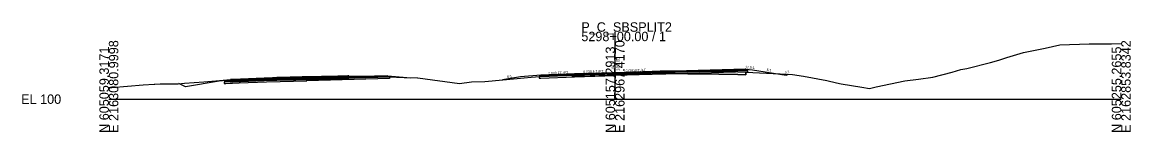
# Model space of a CAD drawing. Extents: x -26 to 1303, y -10 to 12033.
# Drawn here: x -25.7 to 302.8, y 9490.3 to 9522.8 of the extents above; entities that cross this region are included whole.
import ezdxf

# ---------------------------------------------------------------- set-up
doc = ezdxf.new("R2010")
doc.units = 0
for name, color, linetype in [('RD_GPK_XS_Cell', 7, 'Continuous'), ('RD_XS_Base', 7, 'Continuous'), ('RD_XS_ExGround', 7, 'Continuous'), ('RD_XS_ExPaveRet', 7, 'Continuous'), ('RD_XS_Greenside', 7, 'Continuous'), ('RD_XS_Pave', 7, 'Continuous'), ('RD_XS_PaveOvlay_CP', 7, 'Continuous'), ('RD_XS_TieSlope', 7, 'Continuous'), ('RD_XS_TX_Elev_EX', 7, 'Continuous'), ('RD_XS_TX_Elev_PR', 7, 'Continuous'), ('RD_XS_TX_ShdSlope', 7, 'Continuous'), ('RD_XS_TX_Slope', 7, 'Continuous')]:
    doc.layers.add(name, color=color, linetype=linetype)

msp = doc.modelspace()

# ---------------------------------------------------------------- linework, layer by layer
at = {"layer": 'RD_GPK_XS_Cell'}
for p, q in [((150, 9500), (150, 9520)), ((0, 9500), (150, 9500)), ((150, 9500), (300, 9500))]:
    msp.add_line(p, q, dxfattribs=at)
at = {"layer": 'RD_XS_Base'}
for p, q in [((150, 9507.5), (188.73, 9508.58)), ((189.23, 9508.09), (150, 9507)), ((162, 9507.83), (162, 9507.83)), ((162, 9507.83), (162, 9507.83)), ((188.73, 9508.58), (188.73, 9508.58)), ((189.23, 9508.59), (189.23, 9508.09)), ((189.23, 9508.56), (189.23, 9508.56)), ((34.33, 9505.17), (34.17, 9505.16)), ((34.17, 9505.16), (34.17, 9504.82)), ((34.17, 9504.82), (34.17, 9504.66)), ((34.17, 9504.66), (34.33, 9504.67)), ((34.67, 9505.18), (34.33, 9505.17)), ((34.33, 9504.67), (34.67, 9504.68)), ((38.62, 9505.34), (34.67, 9505.18)), ((34.67, 9504.68), (38.62, 9504.84)), ((46.67, 9505.66), (38.62, 9505.34)), ((38.62, 9504.84), (46.67, 9505.16)), ((50.74, 9505.77), (46.67, 9505.66)), ((46.67, 9505.16), (50.74, 9505.27)), ((58.67, 9505.97), (50.74, 9505.77)), ((50.74, 9505.27), (58.67, 9505.47)), ((58.67, 9505.97), (83.17, 9506.61)), ((58.67, 9505.47), (58.67, 9506.13)), ((58.67, 9506.13), (58.67, 9506.13)), ((58.67, 9506.13), (58.67, 9506.13)), ((58.67, 9506.13), (58.67, 9505.97)), ((83.17, 9506.11), (58.67, 9505.47)), ((58.67, 9505.97), (58.67, 9505.97)), ((58.67, 9505.47), (58.67, 9505.97)), ((58.67, 9505.97), (58.67, 9505.97)), ((58.67, 9505.97), (58.67, 9505.97)), ((58.67, 9505.47), (58.67, 9505.47)), ((82.67, 9506.6), (82.67, 9506.6)), ((82.67, 9506.6), (82.67, 9506.6)), ((82.67, 9506.6), (82.67, 9506.6)), ((82.67, 9506.1), (82.67, 9506.1)), ((82.67, 9506.1), (82.67, 9506.1)), ((83.17, 9506.61), (83.17, 9506.11)), ((83.17, 9506.58), (83.17, 9506.58)), ((128, 9506.76), (127.5, 9506.74)), ((127.5, 9506.74), (127.5, 9506.74)), ((127.5, 9506.74), (127.5, 9506.24)), ((127.5, 9506.24), (128, 9506.26)), ((138, 9507.16), (128, 9506.76)), ((128, 9506.76), (128, 9506.76)), ((128, 9506.26), (138, 9506.66)), ((128, 9506.26), (128, 9506.26)), ((136, 9507.08), (136, 9507.08)), ((136, 9506.58), (136, 9506.58)), ((150, 9507.5), (138, 9507.16)), ((138, 9506.66), (150, 9507)), ((150, 9507), (150, 9507.65)), ((150, 9507.65), (150, 9507.65)), ((150, 9507.65), (150, 9507.65)), ((150, 9507.65), (150, 9507.5)), ((150, 9507.5), (150, 9507.5)), ((150, 9507), (150, 9507.5)), ((150, 9507.5), (150, 9507.5)), ((150, 9507.5), (150, 9507.5)), ((150, 9507), (150, 9507)), ((162, 9507.33), (162, 9507.33)), ((162, 9507.33), (162, 9507.33))]:
    msp.add_line(p, q, dxfattribs=at)
at = {"layer": 'RD_XS_ExGround'}
msp.add_lwpolyline([(0, 9503.43), (0.84, 9503.49), (10.16, 9504.26), (13.42, 9504.49), (13.6, 9504.49), (15.17, 9504.51), (16.77, 9504.51), (18.07, 9504.52), (19.01, 9504.53), (20.53, 9504.59), (22.38, 9504.77), (28.15, 9505.18), (31.69, 9505.48), (36.04, 9505.83), (39.02, 9505.95), (48.53, 9506.36), (52.23, 9506.47), (54.06, 9506.48), (55, 9506.5), (55.2, 9506.5), (55.43, 9506.53), (55.74, 9506.55), (57.27, 9506.58), (59.23, 9506.59), (67.87, 9506.83), (71.13, 9506.94), (75.38, 9506.79), (85.22, 9506.5), (87.49, 9506.44), (91.48, 9506.29), (91.52, 9506.28), (91.55, 9506.28), (91.55, 9506.28), (91.59, 9506.28), (103.87, 9504.6), (107.44, 9505.1), (111.38, 9505.23), (121.03, 9506.1), (125.1, 9506.5), (128.93, 9506.85), (137.35, 9507.43), (142.59, 9507.62), (152.69, 9507.92), (160.96, 9508.2), (163.4, 9508.28), (165.01, 9508.29), (167.43, 9508.33), (171.53, 9508.31), (173.91, 9508.29), (180.74, 9508.16), (186.37, 9508.06), (188.71, 9508.01), (198.94, 9507.56), (202.55, 9507.35), (205.82, 9506.81), (212.73, 9505.51), (215.66, 9504.87), (216.98, 9504.5), (223.11, 9503.55), (225.41, 9503.19), (227.38, 9503.65), (235.89, 9505.46), (239.93, 9505.92), (244.13, 9506.5), (249.9, 9508), (252.48, 9508.82), (254.21, 9509.09), (261.21, 9510.92), (263.72, 9511.56), (266.13, 9512.31), (271, 9513.83), (277.48, 9515.16), (281.82, 9516.07), (290.47, 9516.38), (292.3, 9516.41), (297.03, 9516.4), (297.13, 9516.4), (297.14, 9516.4), (297.15, 9516.41), (300, 9516.55)], dxfattribs=at)
at = {"layer": 'RD_XS_ExPaveRet'}
for points in [[(188.71, 9508.01), (188.71, 9508.01), (188.71, 9507.26), (188.71, 9507.26), (186.37, 9507.31), (186.37, 9507.31), (180.74, 9507.41), (180.74, 9507.41), (173.91, 9507.54), (173.91, 9507.54), (171.53, 9507.56), (171.53, 9507.56), (171.53, 9507.56), (167.43, 9507.58), (167.43, 9507.58), (165.01, 9507.54), (165.01, 9507.54), (163.4, 9507.53), (160.96, 9507.45), (160.96, 9507.45), (152.69, 9507.17), (152.69, 9507.17), (152.69, 9507.17), (142.59, 9506.87), (142.59, 9506.87), (137.35, 9506.68), (137.35, 9506.68), (137.35, 9507.43), (142.59, 9507.62), (142.59, 9507.62), (152.69, 9507.92), (152.69, 9507.92), (152.69, 9507.92), (160.96, 9508.2), (160.96, 9508.2), (163.4, 9508.28), (165.01, 9508.29), (165.01, 9508.29), (167.43, 9508.33), (167.43, 9508.33), (171.53, 9508.31), (171.53, 9508.31), (171.53, 9508.31), (173.91, 9508.29), (173.91, 9508.29), (180.74, 9508.16), (180.74, 9508.16), (186.37, 9508.06), (186.37, 9508.06), (188.71, 9508.01), (188.71, 9508.01)], [(188.71, 9508.01), (186.37, 9508.06), (180.74, 9508.16), (173.91, 9508.29), (171.53, 9508.31), (167.43, 9508.33), (165.01, 9508.29), (163.4, 9508.28), (160.96, 9508.2), (152.69, 9507.92), (142.59, 9507.62), (137.35, 9507.43), (137.35, 9506.68), (142.59, 9506.87), (152.69, 9507.17), (160.96, 9507.45), (163.4, 9507.53), (165.01, 9507.54), (167.43, 9507.58), (171.53, 9507.56), (173.91, 9507.54), (180.74, 9507.41), (186.37, 9507.31), (188.71, 9507.26), (188.71, 9507.26), (188.71, 9508.01), (188.71, 9508.01)], [(71.13, 9506.94), (70.78, 9506.93), (67.87, 9506.83), (62.97, 9506.7), (59.23, 9506.59), (58.36, 9506.59), (57.27, 9506.58), (55.9, 9506.56), (55.74, 9506.55), (55.71, 9506.55), (55.68, 9506.55), (55.4, 9506.53), (55.11, 9506.52), (54.98, 9506.51), (54.61, 9506.51), (53.73, 9506.49), (51.93, 9506.44), (51.34, 9506.44), (49.75, 9506.39), (48.53, 9506.36), (45.98, 9506.25), (39.02, 9505.95), (36.68, 9505.86), (36.04, 9505.83), (36.04, 9505.36), (36.04, 9505.08), (36.68, 9505.11), (39.02, 9505.2), (45.98, 9505.5), (48.53, 9505.61), (49.75, 9505.64), (51.34, 9505.69), (51.93, 9505.69), (53.73, 9505.74), (54.61, 9505.76), (54.98, 9505.76), (55.11, 9505.77), (55.4, 9505.78), (55.68, 9505.8), (55.71, 9505.8), (55.74, 9505.8), (55.9, 9505.81), (57.27, 9505.83), (58.36, 9505.84), (59.23, 9505.84), (62.97, 9505.95), (67.87, 9506.08), (70.78, 9506.18), (71.13, 9506.19), (71.13, 9506.19), (71.13, 9506.19), (71.13, 9506.51), (71.13, 9506.94), (71.13, 9506.94), (71.13, 9506.94)], [(71.13, 9506.94), (70.78, 9506.93), (67.87, 9506.83), (62.97, 9506.7), (59.23, 9506.59), (58.36, 9506.59), (57.27, 9506.58), (55.9, 9506.56), (55.74, 9506.55), (55.71, 9506.55), (55.68, 9506.55), (55.4, 9506.53), (55.11, 9506.52), (54.98, 9506.51), (54.61, 9506.51), (53.73, 9506.49), (51.93, 9506.44), (51.34, 9506.44), (49.75, 9506.39), (48.53, 9506.36), (45.98, 9506.25), (39.02, 9505.95), (36.68, 9505.86), (36.04, 9505.83), (36.04, 9505.36), (36.04, 9505.08), (36.68, 9505.11), (39.02, 9505.2), (45.98, 9505.5), (48.53, 9505.61), (49.75, 9505.64), (51.34, 9505.69), (51.93, 9505.69), (53.73, 9505.74), (54.61, 9505.76), (54.98, 9505.76), (55.11, 9505.77), (55.4, 9505.78), (55.68, 9505.8), (55.71, 9505.8), (55.74, 9505.8), (55.9, 9505.81), (57.27, 9505.83), (58.36, 9505.84), (59.23, 9505.84), (62.97, 9505.95), (67.87, 9506.08), (70.78, 9506.18), (71.13, 9506.19), (71.13, 9506.19), (71.13, 9506.51), (71.13, 9506.94), (71.13, 9506.94)]]:
    msp.add_lwpolyline(points, dxfattribs=at)
at = {"layer": 'RD_XS_Greenside'}
for p, q in [((190.73, 9508.74), (200.73, 9507.07)), ((22.67, 9503.67), (20.73, 9504.64)), ((32.67, 9505.34), (22.67, 9503.67)), ((122, 9506.6), (116.62, 9505.7)), ((122, 9506.6), (122, 9506.6)), ((200.73, 9507.07), (201.43, 9507.42))]:
    msp.add_line(p, q, dxfattribs=at)
at = {"layer": 'RD_XS_Pave'}
for p, q in [((150, 9507.81), (138, 9507.48)), ((188.73, 9508.9), (150, 9507.81)), ((188.73, 9508.74), (150, 9507.65)), ((150, 9507.65), (188.73, 9508.74)), ((150, 9507.5), (189.23, 9508.59)), ((150, 9507.81), (150, 9507.81)), ((162, 9508.15), (162, 9508.15)), ((162, 9508.15), (162, 9508.15)), ((162, 9507.99), (162, 9507.99)), ((162, 9507.99), (162, 9507.99)), ((162, 9507.99), (162, 9507.99)), ((162, 9507.99), (162, 9507.99)), ((162, 9507.83), (162, 9507.83)), ((162, 9507.83), (162, 9507.83)), ((188.73, 9508.74), (188.73, 9508.9)), ((188.73, 9508.9), (188.73, 9508.9)), ((188.73, 9508.58), (188.73, 9508.74)), ((188.73, 9508.74), (188.73, 9508.74)), ((38.62, 9505.66), (34.67, 9505.5)), ((34.67, 9505.5), (34.67, 9505.39)), ((34.67, 9505.34), (38.62, 9505.5)), ((38.62, 9505.5), (34.67, 9505.34)), ((34.67, 9505.39), (34.67, 9505.34)), ((34.67, 9505.34), (34.67, 9505.23)), ((34.67, 9505.18), (38.62, 9505.34)), ((34.67, 9505.23), (34.67, 9505.18)), ((46.67, 9505.98), (38.62, 9505.66)), ((38.62, 9505.5), (46.67, 9505.82)), ((46.67, 9505.82), (38.62, 9505.5)), ((38.62, 9505.34), (46.67, 9505.66)), ((50.74, 9506.08), (46.67, 9505.98)), ((46.67, 9505.82), (50.74, 9505.93)), ((50.74, 9505.93), (46.67, 9505.82)), ((46.67, 9505.66), (50.74, 9505.77)), ((58.67, 9506.29), (50.74, 9506.08)), ((50.74, 9505.93), (58.67, 9506.13)), ((58.67, 9506.13), (50.74, 9505.93)), ((50.74, 9505.77), (58.67, 9505.97)), ((82.67, 9506.91), (58.67, 9506.29)), ((82.67, 9506.76), (58.67, 9506.13)), ((58.67, 9506.13), (82.67, 9506.76)), ((58.67, 9505.97), (82.67, 9506.6)), ((58.67, 9506.29), (58.67, 9506.29)), ((58.67, 9506.13), (58.67, 9506.13)), ((58.67, 9506.13), (58.67, 9506.13)), ((58.67, 9506.13), (58.67, 9505.97)), ((58.67, 9506.13), (58.67, 9506.13)), ((58.67, 9505.97), (58.67, 9506.13)), ((58.67, 9506.13), (58.67, 9506.13)), ((58.67, 9506.13), (58.67, 9506.13)), ((58.67, 9505.97), (58.67, 9505.97)), ((58.67, 9505.97), (58.67, 9505.97)), ((82.67, 9506.76), (82.67, 9506.91)), ((82.67, 9506.91), (82.67, 9506.91)), ((82.67, 9506.91), (82.67, 9506.91)), ((82.67, 9506.91), (82.67, 9506.91)), ((82.67, 9506.6), (82.67, 9506.76)), ((82.67, 9506.76), (82.67, 9506.76)), ((82.67, 9506.76), (82.67, 9506.76)), ((82.67, 9506.76), (82.67, 9506.76)), ((82.67, 9506.76), (82.67, 9506.76)), ((82.67, 9506.76), (82.67, 9506.76)), ((82.67, 9506.6), (82.67, 9506.6)), ((82.67, 9506.6), (82.67, 9506.6)), ((138, 9507.48), (128, 9507.08)), ((128, 9506.92), (138, 9507.32)), ((138, 9507.32), (128, 9506.92)), ((128, 9506.76), (138, 9507.16)), ((128, 9507.08), (128, 9507.08)), ((128, 9507.08), (128, 9506.92)), ((128, 9506.92), (128, 9506.92)), ((128, 9506.92), (128, 9506.76)), ((136, 9507.4), (136, 9507.4)), ((136, 9507.24), (136, 9507.24)), ((136, 9507.24), (136, 9507.24)), ((136, 9507.08), (136, 9507.08)), ((138, 9507.32), (150, 9507.65)), ((150, 9507.65), (138, 9507.32)), ((138, 9507.16), (150, 9507.5)), ((150, 9507.65), (150, 9507.65)), ((150, 9507.65), (150, 9507.65)), ((150, 9507.65), (150, 9507.5)), ((150, 9507.65), (150, 9507.65)), ((150, 9507.5), (150, 9507.65)), ((150, 9507.65), (150, 9507.65)), ((150, 9507.65), (150, 9507.65)), ((150, 9507.5), (150, 9507.5)), ((150, 9507.5), (150, 9507.5))]:
    msp.add_line(p, q, dxfattribs=at)
at = {"layer": 'RD_XS_PaveOvlay_CP'}
for p, q in [((150, 9507.81), (138, 9507.48)), ((188.73, 9508.9), (150, 9507.81)), ((150, 9507.81), (150, 9507.81)), ((162, 9508.15), (162, 9508.15)), ((162, 9508.15), (162, 9508.15)), ((38.62, 9505.66), (34.67, 9505.5)), ((46.67, 9505.98), (38.62, 9505.66)), ((50.74, 9506.08), (46.67, 9505.98)), ((58.67, 9506.29), (50.74, 9506.08)), ((82.67, 9506.91), (58.67, 9506.29)), ((58.67, 9506.29), (58.67, 9506.29)), ((82.67, 9506.91), (82.67, 9506.91)), ((82.67, 9506.91), (82.67, 9506.91)), ((138, 9507.48), (128, 9507.08)), ((136, 9507.4), (136, 9507.4))]:
    msp.add_line(p, q, dxfattribs=at)
at = {"layer": 'RD_XS_TieSlope'}
for p, q in [((188.73, 9508.9), (190.73, 9508.74)), ((34.67, 9505.5), (32.67, 9505.34)), ((82.67, 9506.91), (89.51, 9506.36)), ((128, 9507.08), (122, 9506.6))]:
    msp.add_line(p, q, dxfattribs=at)

# ---------------------------------------------------------------- texts
at = {"layer": 'RD_GPK_XS_Cell'}
for s, p in [('P_C_SBSPLIT2', (140, 9520)), ('5298+00.00 / 1', (140, 9517.2)), ('EL 100', (-26, 9498.6))]:
    msp.add_text(s, height=2.8, dxfattribs=at).set_placement(p)
for s, p in [('N 605059.3171', (0, 9490)), ('E 2163080.9998', (2.8, 9490)), ('N 605157.2913', (150, 9490)), ('E 2162967.4170', (152.8, 9490)), ('N 605255.2655', (300, 9490)), ('E 2162853.8342', (302.8, 9490))]:
    msp.add_text(s, height=2.8, rotation=90, dxfattribs=at).set_placement(p)
at = {"layer": 'RD_XS_TX_Elev_EX'}
msp.add_text('107.84', height=0.6, rotation=90, dxfattribs=at).set_placement((149.58, 9508.74))
at = {"layer": 'RD_XS_TX_Elev_PR'}
msp.add_text('107.81', height=1, rotation=90, dxfattribs=at).set_placement((151.39, 9508.36))
at = {"layer": 'RD_XS_TX_ShdSlope'}
msp.add_text('12.5:1', height=0.75, rotation=355.4261, dxfattribs=at).set_placement((188.5, 9509.19))
at = {"layer": 'RD_XS_TX_Slope'}
for s, rotation, p in [('0.040 FT./FT.', 2.2906, (130.15, 9507.28)), ('0.030 FT./FT.', 1.7184, (140.55, 9507.74)), ('0.030 FT./FT.', 1.7184, (153.16, 9508.08)), ('6:1', 350.5358, (194.87, 9508.42)), ('2:1', 26.5651, (200.53, 9507.33)), ('6:1', 9.4623, (118.07, 9506.23))]:
    msp.add_text(s, height=0.75, rotation=rotation, dxfattribs=at).set_placement(p)

doc.saveas('drawing.dxf')
